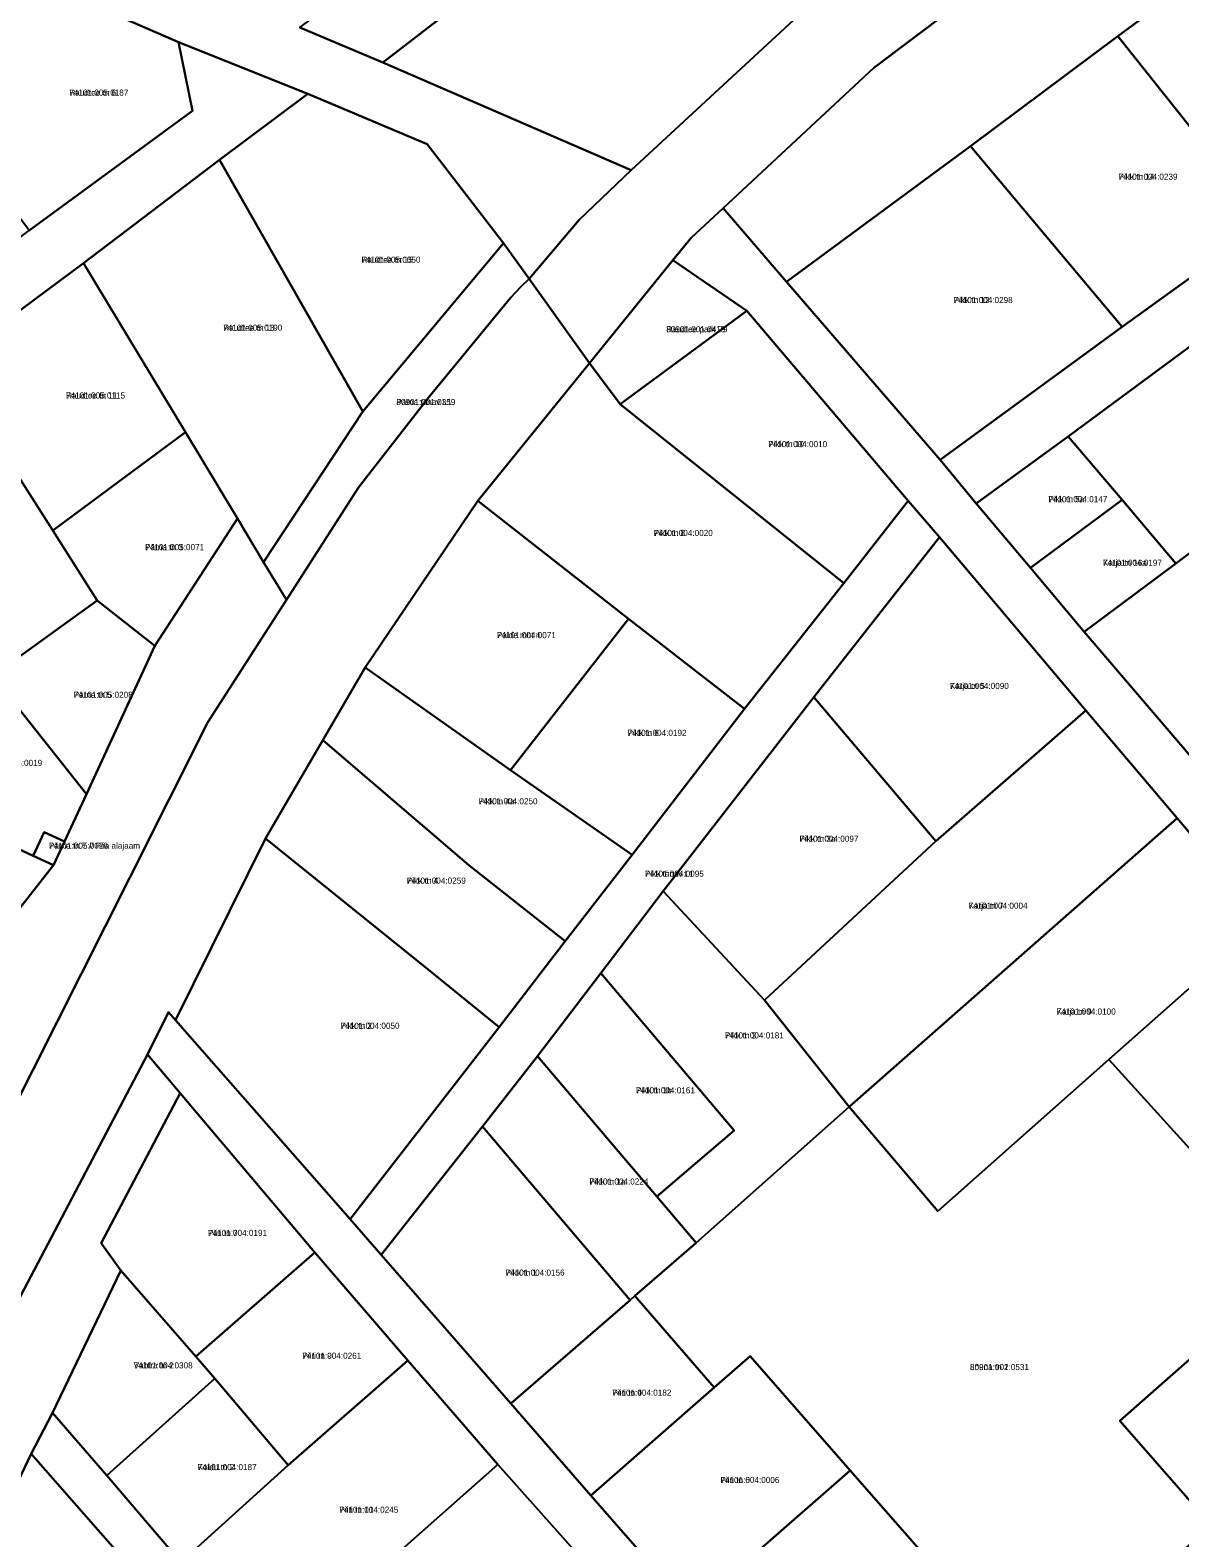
# Model space of a CAD drawing. Extents: x 524000 to 564260, y 6469338 to 6496391.
# Drawn here: x 537974.1 to 538256.7, y 6473256.9 to 6473627.5 of the extents above; entities that cross this region are included whole.
import ezdxf

# ---------------------------------------------------------------- set-up
doc = ezdxf.new("R2010")
doc.units = 0
for name, color, linetype in [('L_AADRESS', 7, 'Continuous'), ('PIIR', 7, 'Continuous'), ('TUNNUS', 7, 'Continuous')]:
    doc.layers.add(name, color=color, linetype=linetype)

msp = doc.modelspace()

# ---------------------------------------------------------------- linework, layer by layer
at = {"layer": 'PIIR'}
for points in [[(538211.96, 6473766.71), (538228.08, 6473748.54), (538200.24, 6473727.49), (538176.12, 6473709.65), (538149.59, 6473690.03), (538180.94, 6473647.73), (538181.82, 6473646.52), (538177.35, 6473642.97), (538168.14, 6473655.71), (538146.49, 6473685.63), (538126.68, 6473670.37), (538060.74, 6473619.57), (538040.37, 6473628.2), (538067.49, 6473648.43), (538093.27, 6473667.58), (538115.56, 6473684.46), (538137.44, 6473700.93), (538157.34, 6473715.99), (538187.76, 6473739.02), (538183.32, 6473744.95)], [(538121.81, 6473593.12), (538060.74, 6473619.57), (538126.68, 6473670.37), (538148.39, 6473641.05), (538168.14, 6473655.71), (538177.35, 6473642.97), (538166.08, 6473634.03)], [(538277.99, 6473580.22), (538241.41, 6473626.07), (538278.34, 6473653.23), (538313.26, 6473606.67)], [(537952.53, 6473606.66), (537955.27, 6473614.75), (537964.47, 6473644.63), (538010.52, 6473624.6), (538014, 6473607.71), (537973.77, 6473578.26)], [(538010.52, 6473624.6), (538042.3, 6473611.92), (538020.62, 6473595.63), (537987.2, 6473570.28), (537953.54, 6473545.34), (537920.36, 6473520.58), (537861.87, 6473476.79), (537844.52, 6473463.73), (537820.14, 6473444.71), (537806.67, 6473434.95), (537793.95, 6473425.71), (537788.26, 6473421.58), (537751.21, 6473394.37), (537754.58, 6473413.98), (537847.44, 6473483.75), (537883.48, 6473510.79), (537929.92, 6473545.34), (537973.77, 6473578.26), (538014, 6473607.71)], [(538242.54, 6473554.64), (538205.24, 6473599), (538241.41, 6473626.07), (538277.99, 6473580.22)], [(538055.85, 6473533.82), (538020.62, 6473595.63), (538042.3, 6473611.92), (538071.66, 6473599.48), (538090.39, 6473575.22)], [(538160, 6473565.72), (538205.24, 6473599), (538242.54, 6473554.64), (538197.76, 6473521.93)], [(537987.2, 6473570.28), (538020.62, 6473595.63), (538055.85, 6473533.82), (538031.44, 6473496.78), (538025, 6473507.48), (538012.22, 6473528.71)], [(538054.77, 6473515.09), (538037.04, 6473487.48), (538031.44, 6473496.78), (538055.85, 6473533.82), (538090.39, 6473575.22), (538096.73, 6473566.39), (538094.7, 6473564.49), (538092.25, 6473561.84), (538089.08, 6473558.08), (538072.04, 6473537.32)], [(537987.2, 6473570.28), (538012.22, 6473528.71), (537979.65, 6473504.52), (537953.54, 6473545.34)], [(538150.28, 6473558.52), (538119.07, 6473535.59), (538111.56, 6473545.72), (538132.07, 6473571)], [(538276.94, 6473562.9), (538302.64, 6473531.61), (538255.67, 6473496.48), (538242.48, 6473512.09), (538229.23, 6473527.66)], [(538174.11, 6473491.57), (538119.07, 6473535.59), (538150.28, 6473558.52), (538189.9, 6473511.88)], [(537953.54, 6473545.34), (537979.65, 6473504.52), (537990.53, 6473487.32), (537964.78, 6473468.79), (537964.02, 6473468.33), (537953.42, 6473460.71), (537920.36, 6473520.58)], [(538084.14, 6473511.85), (538111.56, 6473545.72), (538119.07, 6473535.59), (538174.11, 6473491.57), (538149.7, 6473460.69), (538121.18, 6473482.85)], [(537979.65, 6473504.52), (538012.22, 6473528.71), (538025, 6473507.48), (538004.74, 6473476.19), (537990.53, 6473487.32)], [(538233.2, 6473479.68), (538255.67, 6473496.48), (538302.64, 6473531.61), (538329.09, 6473499.91), (538260.75, 6473447.38)], [(538206.62, 6473511.19), (538229.23, 6473527.66), (538242.48, 6473512.09), (538219.98, 6473495.36)], [(538197.64, 6473502.94), (538166.75, 6473463.57), (538129.68, 6473415.9), (538114.31, 6473395.71), (538098.8, 6473375.36), (538085.26, 6473358.09), (538060.31, 6473326.47), (538052.7, 6473335.3), (538089.39, 6473382.47), (538105.54, 6473403.64), (538122.03, 6473424.85), (538149.7, 6473460.69), (538174.11, 6473491.57), (538189.9, 6473511.88)], [(538056.41, 6473470.88), (538084.14, 6473511.85), (538121.18, 6473482.85), (538092.13, 6473445.61)], [(538219.98, 6473495.36), (538242.48, 6473512.09), (538255.67, 6473496.48), (538233.2, 6473479.68)], [(538166.75, 6473463.57), (538197.64, 6473502.94), (538233.55, 6473460.31), (538196.69, 6473428.22)], [(537987.87, 6473439.78), (537964.78, 6473468.79), (537990.53, 6473487.32), (538004.74, 6473476.19)], [(538121.18, 6473482.85), (538149.7, 6473460.69), (538122.03, 6473424.85), (538092.13, 6473445.61)], [(537938.56, 6473441.35), (537974.82, 6473424.59), (537979.81, 6473422.29), (537967.61, 6473406.75), (537947.16, 6473416.32), (537911.45, 6473432.19), (537901.08, 6473436.32), (537864.09, 6473453.8), (537844.52, 6473463.73), (537861.87, 6473476.79)], [(537964.78, 6473468.79), (537987.87, 6473439.78), (537982.5, 6473428.1), (537977.5, 6473430.4), (537974.82, 6473424.59), (537938.56, 6473441.35), (537953.42, 6473460.71), (537964.02, 6473468.33)], [(538105.54, 6473403.64), (538081.91, 6473422.28), (538046.02, 6473453.04), (538056.41, 6473470.88), (538092.13, 6473445.61), (538122.03, 6473424.85)], [(538166.75, 6473463.57), (538196.69, 6473428.22), (538154.57, 6473389.09), (538129.68, 6473415.9)], [(538196.69, 6473428.22), (538233.55, 6473460.31), (538256.01, 6473433.85), (538175.36, 6473362.86), (538154.57, 6473389.09)], [(538046.02, 6473453.04), (538081.91, 6473422.28), (538105.54, 6473403.64), (538089.39, 6473382.47), (538071.86, 6473396.61), (538031.94, 6473428.82)], [(538175.36, 6473362.86), (538256.01, 6473433.85), (538277.55, 6473408.48), (538239.21, 6473374.5), (538197.23, 6473337.27)], [(537977.5, 6473430.4), (537982.5, 6473428.1), (537979.81, 6473422.29), (537974.82, 6473424.59)], [(538071.86, 6473396.61), (538089.39, 6473382.47), (538052.7, 6473335.3), (538009.78, 6473384.2), (538031.94, 6473428.82)], [(538147.16, 6473357.06), (538114.31, 6473395.71), (538129.68, 6473415.9), (538154.57, 6473389.09), (538175.36, 6473362.86), (538137.81, 6473329.48), (538128.12, 6473340.87)], [(538239.21, 6473374.5), (538277.55, 6473408.48), (538299.8, 6473382.2), (538262.37, 6473349.06)], [(538114.31, 6473395.71), (538147.16, 6473357.06), (538128.12, 6473340.87), (538119.54, 6473350.95), (538098.8, 6473375.36)], [(538002.94, 6473375.76), (538008.07, 6473386.14), (538009.78, 6473384.2), (538052.7, 6473335.3), (538060.31, 6473326.47), (538092.19, 6473289.93), (538111.88, 6473267.35), (538136.48, 6473239.23), (538159.4, 6473213.1), (538181.89, 6473187.71), (538188.63, 6473180.29), (538238.38, 6473124.26), (538229.44, 6473117.4), (538209.36, 6473138.59), (538186.75, 6473163.27), (538165.75, 6473188.27), (538142.79, 6473215.5), (538135.03, 6473222.08), (538110.95, 6473250.31), (538088.99, 6473274.96), (538066.93, 6473300.55), (538044.07, 6473327.05), (538010.97, 6473366.26)], [(538098.8, 6473375.36), (538119.54, 6473350.95), (538128.12, 6473340.87), (538137.81, 6473329.48), (538122.71, 6473316.4), (538121.56, 6473315.4), (538085.26, 6473358.09)], [(538197.23, 6473337.27), (538239.21, 6473374.5), (538262.37, 6473349.06), (538284.96, 6473323.67), (538265.28, 6473306.25), (538241.96, 6473285.71), (538264.5, 6473259.96), (538220.9, 6473221.84), (538198.41, 6473247.54), (538175.67, 6473273.53), (538151.07, 6473301.61), (538142.21, 6473293.86), (538122.71, 6473316.4), (538137.81, 6473329.48), (538175.36, 6473362.86)], [(537991.51, 6473329.38), (538010.97, 6473366.26), (538044.07, 6473327.05), (538014.82, 6473301.53), (537996.31, 6473322.65)], [(538085.26, 6473358.09), (538121.56, 6473315.4), (538092.19, 6473289.93), (538060.31, 6473326.47)], [(538014.82, 6473301.53), (538044.07, 6473327.05), (538066.93, 6473300.55), (538037.45, 6473274.84), (538019.43, 6473296.1)], [(537979.58, 6473287.68), (537996.31, 6473322.65), (538014.82, 6473301.53), (538019.43, 6473296.1), (537992.9, 6473272.24)], [(538092.19, 6473289.93), (538121.56, 6473315.4), (538122.71, 6473316.4), (538142.21, 6473293.86), (538111.88, 6473267.35)], [(538241.96, 6473285.71), (538265.28, 6473306.25), (538287.83, 6473280.48), (538264.5, 6473259.96)], [(538037.45, 6473274.84), (538066.93, 6473300.55), (538088.99, 6473274.96), (538033.3, 6473225.67), (538011.66, 6473251.45)], [(538175.67, 6473273.53), (538136.48, 6473239.23), (538111.88, 6473267.35), (538142.21, 6473293.86), (538151.07, 6473301.61)], [(538019.43, 6473296.1), (538037.45, 6473274.84), (538011.66, 6473251.45), (538011.01, 6473251.05), (537992.9, 6473272.24)], [(537979.58, 6473287.68), (537992.9, 6473272.24), (538011.01, 6473251.05), (538011.66, 6473251.45), (538033.3, 6473225.67), (538054.58, 6473201.22), (538079, 6473173.43), (538072.12, 6473165.95), (538054.09, 6473187.1), (538042.21, 6473200.34), (538028.86, 6473215.53), (538003.68, 6473244.12), (537974.33, 6473277.57)], [(537974.33, 6473277.57), (538003.68, 6473244.12), (537980.89, 6473223.78), (537960.04, 6473247.79)], [(538033.3, 6473225.67), (538088.99, 6473274.96), (538110.95, 6473250.31), (538070.39, 6473215.01), (538054.58, 6473201.22)], [(538136.48, 6473239.23), (538175.67, 6473273.53), (538198.41, 6473247.54), (538159.4, 6473213.1)]]:
    msp.add_lwpolyline(points, close=True, dxfattribs=at)
for points in [[(538273.42, 6473687.55), (538181.5, 6473618.27), (538144.4, 6473583.81), (538136.55, 6473576.51), (538132.07, 6473571), (538111.56, 6473545.72), (538096.73, 6473566.39), (538109.05, 6473580.91), (538121.81, 6473593.12), (538166.08, 6473634.03), (538177.35, 6473642.97), (538181.82, 6473646.52), (538180.94, 6473647.73), (538207.3, 6473667.58), (538231.27, 6473685.62), (538259.09, 6473706.81)], [(538278.34, 6473653.23), (538241.41, 6473626.07), (538205.24, 6473599), (538160, 6473565.72), (538144.4, 6473583.81), (538181.5, 6473618.27), (538273.42, 6473687.55)], [(538040.37, 6473628.2), (538060.74, 6473619.57), (538121.81, 6473593.12), (538109.05, 6473580.91), (538096.73, 6473566.39), (538090.39, 6473575.22), (538071.66, 6473599.48), (538042.3, 6473611.92), (538010.52, 6473624.6), (537964.47, 6473644.63)], [(538277.55, 6473408.48), (538256.01, 6473433.85), (538233.55, 6473460.31), (538197.64, 6473502.94), (538189.9, 6473511.88), (538150.28, 6473558.52), (538132.07, 6473571), (538136.55, 6473576.51), (538144.4, 6473583.81), (538160, 6473565.72), (538197.76, 6473521.93), (538206.62, 6473511.19), (538219.98, 6473495.36), (538233.2, 6473479.68), (538260.75, 6473447.38)], [(538276.94, 6473562.9), (538229.23, 6473527.66), (538206.62, 6473511.19), (538197.76, 6473521.93), (538242.54, 6473554.64), (538277.99, 6473580.22)], [(537899.34, 6473222.91), (537923.04, 6473270.09), (537936.29, 6473295.74), (537974.68, 6473371.89), (537998.55, 6473419.28), (538017.73, 6473457.41), (538037.04, 6473487.48), (538054.77, 6473515.09), (538072.04, 6473537.32), (538089.08, 6473558.08), (538092.25, 6473561.84), (538094.7, 6473564.49), (538096.73, 6473566.39), (538111.56, 6473545.72), (538084.14, 6473511.85), (538056.41, 6473470.88), (538046.02, 6473453.04), (538031.94, 6473428.82), (538009.78, 6473384.2), (538008.07, 6473386.14), (538002.94, 6473375.76), (537956.46, 6473287.47), (537881.05, 6473130.21)], [(537886.07, 6473239.61), (537902.82, 6473273.77), (537911.15, 6473290.63), (537919.48, 6473307.48), (537927.81, 6473324.33), (537945.7, 6473360.45), (537967.61, 6473406.75), (537979.81, 6473422.29), (537982.5, 6473428.1), (537987.87, 6473439.78), (538004.74, 6473476.19), (538025, 6473507.48), (538031.44, 6473496.78), (538037.04, 6473487.48), (538017.73, 6473457.41), (537998.55, 6473419.28), (537974.68, 6473371.89), (537936.29, 6473295.74), (537923.04, 6473270.09), (537899.34, 6473222.91)], [(537881.05, 6473130.21), (537956.46, 6473287.47), (538002.94, 6473375.76), (538010.97, 6473366.26), (537991.51, 6473329.38), (537996.31, 6473322.65), (537979.58, 6473287.68), (537974.33, 6473277.57), (537960.04, 6473247.79)]]:
    msp.add_lwpolyline(points, dxfattribs=at)

# ---------------------------------------------------------------- texts
at = {"layer": 'L_AADRESS'}
for s, p in [('Raudtee tn 6', (537983.69, 6473611.45)), ('Pikk tn 14', (538241.62, 6473590.78)), ('Raudtee tn 15', (538055.5, 6473570.38)), ('Pikk tn 12', (538201.09, 6473560.46)), ('Raudtee tn 13', (538021.53, 6473553.65)), ('Raudtee park P9', (538130.44, 6473553.29)), ('Raudtee tn 11', (537982.88, 6473537)), ('Pärna tänav L1', (538064.08, 6473535.39)), ('Pikk tn 10', (538155.49, 6473525.04)), ('Pikk tn 5a', (538224.38, 6473511.51)), ('Pikk tn 8', (538127.37, 6473503.21)), ('Pärna tn 3', (538002.32, 6473499.72)), ('Karja tn 16a', (538237.78, 6473495.88)), ('Paide mnt 4', (538088.79, 6473478.09)), ('Karja tn 5', (538200.15, 6473465.6)), ('Pärna tn 5', (537984.76, 6473463.43)), ('Pikk tn 6', (538120.92, 6473454.07)), ('Pikk tn 4a', (538084.29, 6473437.26)), ('Pikk tn 3a', (538163.18, 6473428.04)), ('Pärna tn 7 // Piia alajaam', (537978.66, 6473426.34)), ('Pikk tänav L1', (538125.17, 6473419.45)), ('Pikk tn 4', (538066.65, 6473417.75)), ('Karja tn 7', (538204.75, 6473411.58)), ('Pikk tn 2', (538050.36, 6473382.06)), ('Karja tn 9', (538226.42, 6473385.56)), ('Pikk tn 3', (538144.84, 6473379.69)), ('Pikk tn 1b', (538122.98, 6473366.21)), ('Pikk tn 1a', (538111.54, 6473343.78)), ('Piiri tn 7', (538017.79, 6473331.15)), ('Pikk tn 1', (538090.94, 6473321.39)), ('Piiri tn 9', (538040.95, 6473300.95)), ('Vahtra tn 2', (537999.5, 6473298.59)), ('Lõuna tn 2', (538205.1, 6473298.17)), ('Piiri tn 4', (538117.19, 6473291.88)), ('Koidu tn 2', (538015.22, 6473273.58)), ('Piiri tn 6', (538143.75, 6473270.42)), ('Piiri tn 11', (538050.06, 6473263.11))]:
    msp.add_text(s, height=1.5, dxfattribs=at).set_placement(p)
at = {"layer": 'TUNNUS'}
for s, p in [('74101:005:0187', (537983.69, 6473611.45)), ('74101:004:0239', (538241.62, 6473590.78)), ('74101:005:0050', (538055.5, 6473570.38)), ('74101:004:0298', (538201.09, 6473560.46)), ('74101:005:0190', (538021.53, 6473553.65)), ('80901:001:0419', (538130.44, 6473553.29)), ('74101:005:0115', (537982.88, 6473537)), ('80901:001:0359', (538064.08, 6473535.39)), ('74101:004:0010', (538155.49, 6473525.04)), ('74101:004:0147', (538224.38, 6473511.51)), ('74101:004:0020', (538127.37, 6473503.21)), ('74101:005:0071', (538002.32, 6473499.72)), ('74101:004:0197', (538237.78, 6473495.88)), ('74101:004:0071', (538088.79, 6473478.09)), ('74101:004:0090', (538200.15, 6473465.6)), ('74101:005:0208', (537984.76, 6473463.43)), ('74101:004:0192', (538120.92, 6473454.07)), ('74101:005:0019', (537962.51, 6473446.69)), ('74101:004:0250', (538084.29, 6473437.26)), ('74101:004:0097', (538163.18, 6473428.04)), ('74101:005:0026', (537978.66, 6473426.34)), ('74101:004:0095', (538125.17, 6473419.45)), ('74101:004:0259', (538066.65, 6473417.75)), ('74101:004:0004', (538204.75, 6473411.58)), ('74101:004:0050', (538050.36, 6473382.06)), ('74101:004:0100', (538226.42, 6473385.56)), ('74101:004:0181', (538144.84, 6473379.69)), ('74101:004:0161', (538122.98, 6473366.21)), ('74101:004:0224', (538111.54, 6473343.78)), ('74101:004:0191', (538017.79, 6473331.15)), ('74101:004:0156', (538090.94, 6473321.39)), ('74101:004:0261', (538040.95, 6473300.95)), ('74101:004:0308', (537999.5, 6473298.59)), ('80901:001:0531', (538205.1, 6473298.17)), ('74101:004:0182', (538117.19, 6473291.88)), ('74101:004:0187', (538015.22, 6473273.58)), ('74101:004:0006', (538143.75, 6473270.42)), ('74101:004:0245', (538050.06, 6473263.11))]:
    msp.add_text(s, height=1.5, dxfattribs=at).set_placement(p)

doc.saveas('drawing.dxf')
